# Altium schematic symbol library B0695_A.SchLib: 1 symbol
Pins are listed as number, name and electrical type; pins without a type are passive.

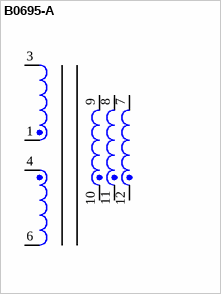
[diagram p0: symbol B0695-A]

## B0695-A
designator T?
Pri:Sec = 1:0.23; Pri:Bias = 1:0.69 Transformer 1500Vrms Isolation; Manufacturer: Coilcraft; SymbolCreator: a0224881; Value: 105uH
footprint B0695-A (1:0.23 and 1:0.69 Transformer)
pins: 1, 3, 4, 6, 7, 8, 9, 10, 11, 12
